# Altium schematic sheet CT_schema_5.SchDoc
size 296 x 198 mm
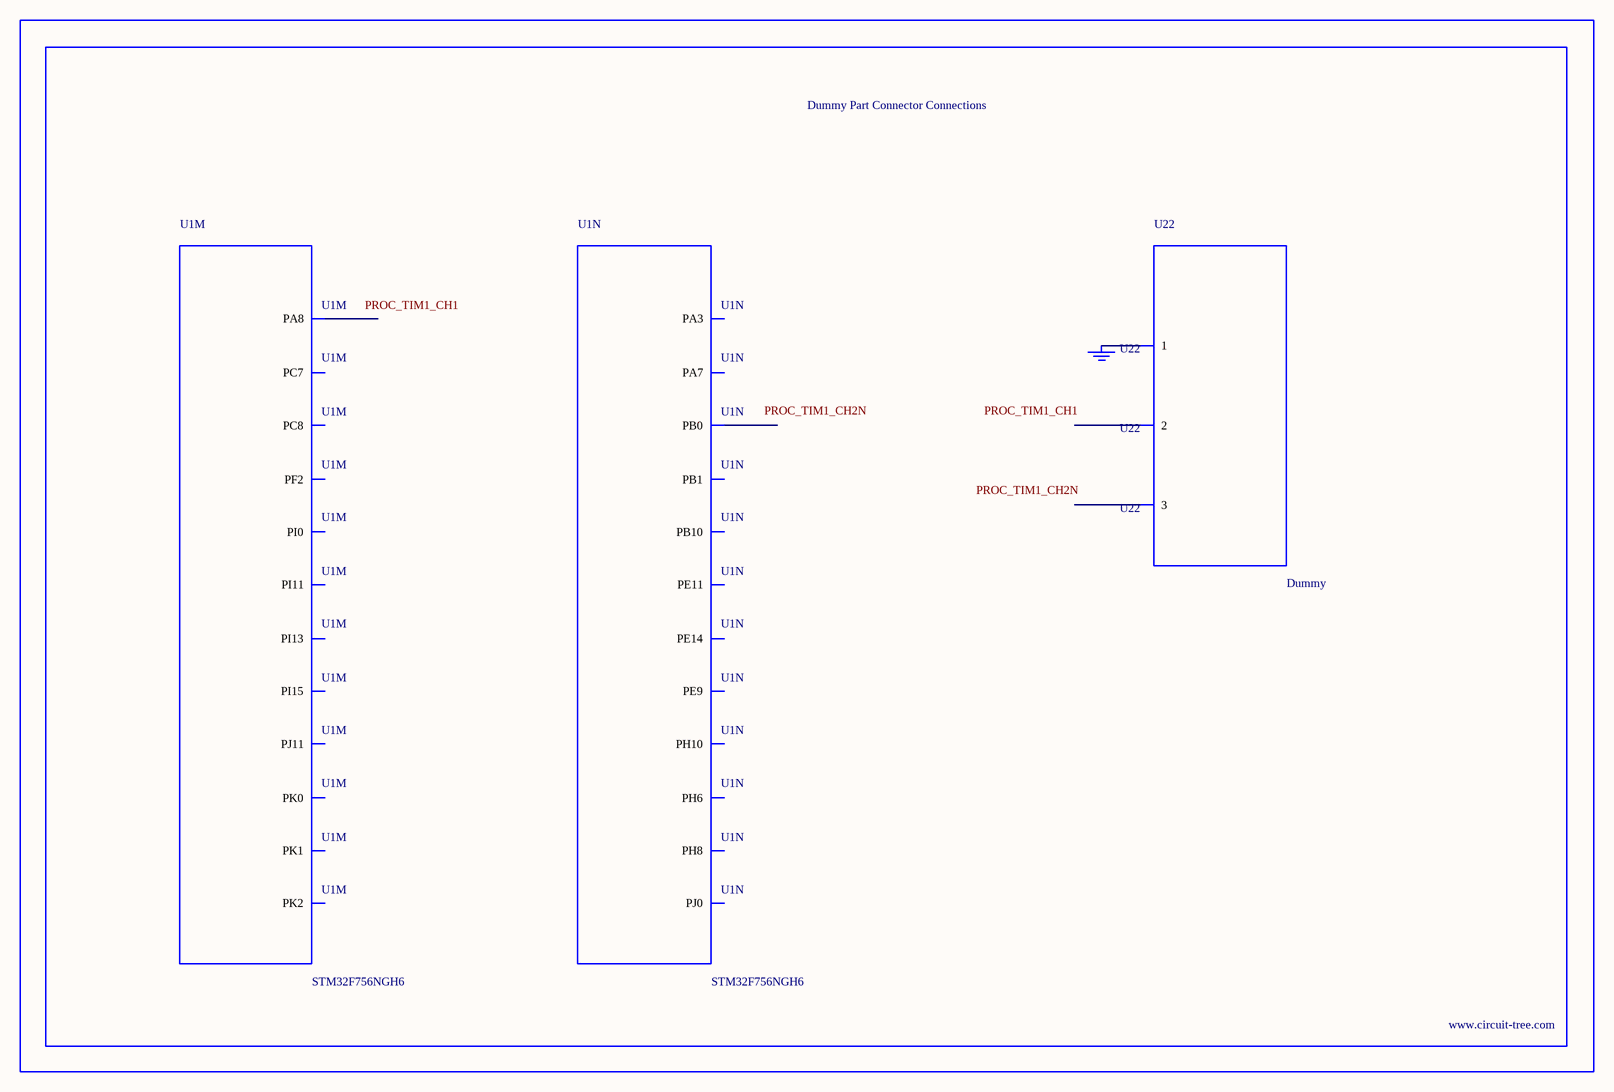
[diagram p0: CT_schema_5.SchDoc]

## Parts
BORDER4  (no value)
GND_INSTANCE_4_0  (no value)
U1  STM32F756NGH6  [TFBGA216]  (parts M,N of 14)
U22  Dummy  [DUMMY_PACKAGE_251]

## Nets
NetGND_INSTANCE_4_0_0: GND_INSTANCE_4_0.0(GND) U22.1

Not connected (* = marked no-connect by the designer): U1 E14(PI0) F3(PI11) F12(PK1) F13(PK2) F15(PA8) G2(PF2) G3(PI13) G4(PI15) G12(PJ11) G13(PK0) G14(PC8) G15(PC7) P9(PE9) P10(PE11) P11(PE14) P12(PB10) P13(PH6) P14(PH8) P15(PH10) R2(PA3) R3(PA7) R4(PB1) R5(PB0) R6(PJ0); U22 2 3

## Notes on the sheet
- Labels drawn without touching a wire or pin: PROC_TIM1_CH1, PROC_TIM1_CH2N

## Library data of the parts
BORDER4 = BORDER_PAGE4
GND_INSTANCE_4_0 = GND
